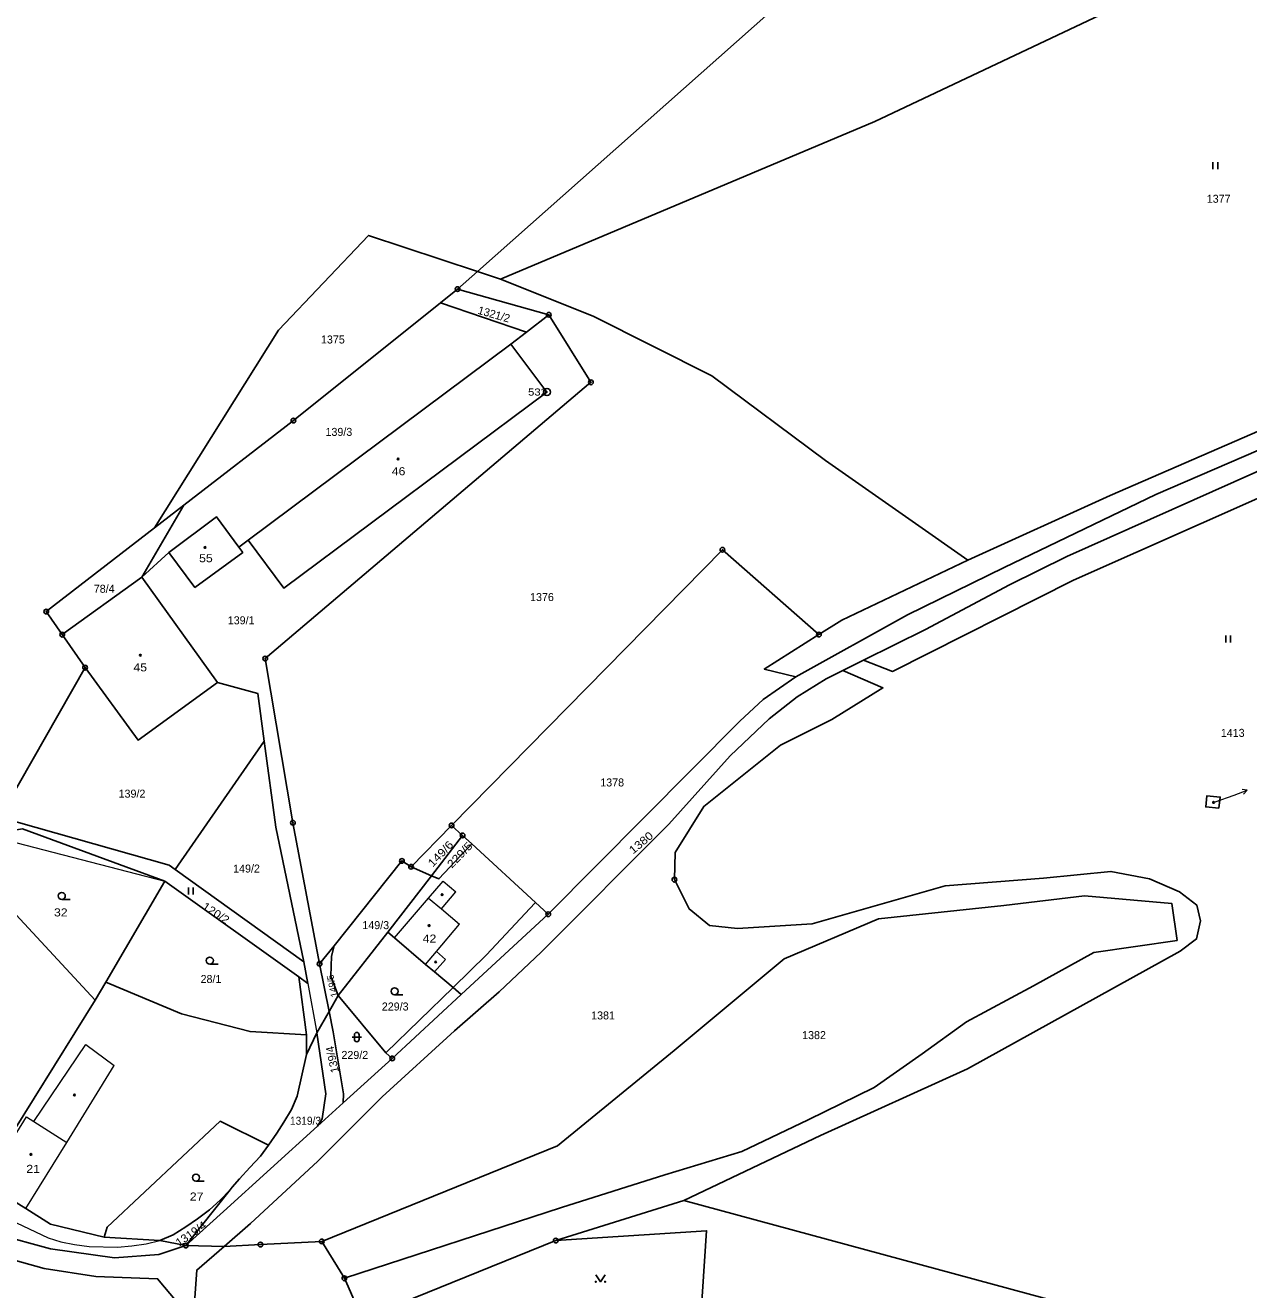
# Model space of a CAD drawing. Extents: x -872229 to -869198, y -1075981 to -1074329.
# Drawn here: x -870924.3 to -870664.3, y -1075205 to -1074936.4 of the extents above; entities that cross this region are included whole.
import ezdxf
from ezdxf.enums import TextEntityAlignment as Align

# ---------------------------------------------------------------- set-up
doc = ezdxf.new("R2010")
doc.units = 0
doc.header["$LTSCALE"] = 0.68
for name, color, linetype, lineweight in [('1', 7, 'Continuous', 25), ('3', 7, 'Continuous', 25), ('4', 7, 'Continuous', 13), ('5', 7, 'Continuous', 25), ('7', 7, 'Continuous', 13), ('8', 7, 'Continuous', 25)]:
    doc.layers.add(name, color=color, linetype=linetype, lineweight=lineweight)
doc.layers.add('2', color=7, linetype='Continuous')

msp = doc.modelspace()

# ---------------------------------------------------------------- linework, layer by layer
at = {"layer": '1'}
for p, q in [((-870832.43, -1074992.44), (-870828.23, -1074988.72)), ((-870828.23, -1074988.72), (-870823.34, -1074990.34)), ((-870832.43, -1074992.44), (-870813.05, -1074997.9)), ((-870817.8, -1075001.55), (-870836.08, -1074995.36)), ((-870821.1, -1075004.1), (-870876.96, -1075045.75)), ((-870890.62, -1075038.35), (-870899.54, -1075053.64)), ((-870896.85, -1075043.16), (-870890.62, -1075038.35)), ((-870876.96, -1075045.75), (-870878.94, -1075047.23)), ((-870893.79, -1075048.39), (-870899.54, -1075053.64)), ((-870916.45, -1075065.85), (-870911.59, -1075072.86)), ((-870837.98, -1075117.09), (-870831.39, -1075108.5)), ((-870892.44, -1075115.73), (-870865.1, -1075135.39)), ((-870837.98, -1075117.09), (-870842.32, -1075115.15)), ((-870857.82, -1075142.49), (-870847.25, -1075129.09)), ((-870858.7, -1075131.95), (-870861.76, -1075135.78)), ((-870907.21, -1075139.69), (-870909.44, -1075143.5)), ((-870857.82, -1075142.49), (-870859.76, -1075145.91)), ((-870856.75, -1075165.32), (-870846.32, -1075155.87)), ((-870862.22, -1075170.28), (-870856.75, -1075165.32)), ((-870784.32, -1075186.07), (-870610.3, -1075233.15)), ((-870907.54, -1075193.83), (-870895.75, -1075194.57)), ((-870895.75, -1075194.57), (-870890.21, -1075195.64)), ((-870890.21, -1075195.64), (-870882.08, -1075195.84)), ((-870856.49, -1075202.6), (-870861.31, -1075194.77))]:
    msp.add_line(p, q, dxfattribs=at)
for points in [[(-870828.23, -1074988.72), (-870733.1, -1074904.34), (-870634.05, -1074816.48)], [(-870823.34, -1074990.34), (-870743.76, -1074956.82), (-870646.76, -1074910.9), (-870624.12, -1074897.23)], [(-870723.96, -1075050), (-870693.71, -1075036.28), (-870649.55, -1075017.06), (-870584.14, -1074987.8), (-870552.32, -1074975.37), (-870546.15, -1074971.5), (-870542.19, -1074967.42)], [(-870896.85, -1075043.16), (-870870.5, -1075001.16), (-870851.34, -1074981.04), (-870828.23, -1074988.72)], [(-870760.55, -1075074.8), (-870736.8, -1075061.65), (-870716.28, -1075051.57), (-870684.01, -1075036.04), (-870643.52, -1075018.55), (-870612.61, -1075004.24), (-870591.23, -1074994.43), (-870570.04, -1074985.9), (-870558.3, -1074982.28), (-870544.73, -1074980.25)], [(-870746.19, -1075071.27), (-870732.98, -1075064.74), (-870715.15, -1075055.28), (-870702.93, -1075049.25), (-870662.75, -1075031.31), (-870646.95, -1075024.02), (-870627.8, -1075016.08), (-870598.46, -1075002.7), (-870582.08, -1074994.97), (-870575.53, -1074992.25), (-870561.97, -1074987.44), (-870555.39, -1074985.35), (-870547.72, -1074984.42), (-870543.16, -1074984.27), (-870536.54, -1074984.58), (-870532.83, -1074984.88), (-870528.68, -1074985.73), (-870515.43, -1074988.43), (-870489.43, -1074993.61)], [(-870723.96, -1075050), (-870735.85, -1075041.72), (-870754.24, -1075028.86), (-870778.4, -1075010.85), (-870803.61, -1074998.16), (-870823.34, -1074990.34)], [(-870890.62, -1075038.35), (-870867.33, -1075020.36), (-870836.08, -1074995.36), (-870832.43, -1074992.44)], [(-870861.76, -1075135.78), (-870867.42, -1075105.8), (-870873.32, -1075070.92), (-870804.09, -1075012.24), (-870813.05, -1074997.9), (-870817.8, -1075001.55), (-870821.1, -1075004.1)], [(-870876.96, -1075045.75), (-870869.36, -1075056), (-870813.44, -1075014.3), (-870821.1, -1075004.1)], [(-870746.19, -1075071.27), (-870740.01, -1075073.65), (-870701.56, -1075054.27), (-870661.14, -1075036.37), (-870626.13, -1075019.06), (-870610.36, -1075011.6)], [(-870916.45, -1075065.85), (-870919.85, -1075060.95), (-870896.85, -1075043.16)], [(-870878.94, -1075047.23), (-870883.7, -1075040.81), (-870893.79, -1075048.39)], [(-870893.79, -1075048.39), (-870888.25, -1075055.83), (-870878.08, -1075048.38), (-870878.94, -1075047.23)], [(-870833.7, -1075106.39), (-870776.15, -1075047.82), (-870755.65, -1075065.84)], [(-870755.65, -1075065.84), (-870750.79, -1075062.78), (-870723.96, -1075050)], [(-870911.59, -1075072.86), (-870900.34, -1075088.23), (-870883.44, -1075076.03), (-870899.54, -1075053.64), (-870916.45, -1075065.85)], [(-870760.55, -1075074.8), (-870767.27, -1075073.18), (-870755.65, -1075065.84)], [(-870882.08, -1075195.84), (-870876.48, -1075190.98), (-870862.11, -1075177.7), (-870848.46, -1075164.05), (-870833.06, -1075150.02), (-870823.61, -1075141.72), (-870814.66, -1075133.34), (-870787.51, -1075106.14), (-870774.51, -1075091.61), (-870766.24, -1075083.76), (-870760.23, -1075079.03), (-870754.08, -1075075.24), (-870750.53, -1075073.45), (-870746.19, -1075071.27)], [(-870930.06, -1075104.56), (-870928.47, -1075102.44), (-870911.59, -1075072.86)], [(-870813.18, -1075125.26), (-870772.47, -1075084.22), (-870767.49, -1075079.65), (-870760.55, -1075074.8)], [(-870784.32, -1075186.07), (-870755.33, -1075172.29), (-870724.06, -1075158.07), (-870678.88, -1075133.11), (-870675.36, -1075130.49), (-870674.52, -1075126.66), (-870675.34, -1075123.32), (-870678.97, -1075120.49), (-870685.35, -1075117.73), (-870693.57, -1075116.15), (-870707.89, -1075117.61), (-870728.84, -1075119.23), (-870757.05, -1075127.29), (-870772.94, -1075128.29), (-870778.87, -1075127.61), (-870783.25, -1075124.12), (-870786.34, -1075117.9), (-870786.18, -1075112.16), (-870780.09, -1075102.34), (-870763.77, -1075089.36), (-870752.86, -1075083.85), (-870742.03, -1075077.18), (-870750.53, -1075073.45)], [(-870883.44, -1075076.03), (-870874.9, -1075078.35), (-870873.52, -1075088.47)], [(-870930.06, -1075104.56), (-870893.7, -1075114.82), (-870892.44, -1075115.73), (-870873.52, -1075088.47)], [(-870873.52, -1075088.47), (-870871.03, -1075106.76), (-870865.1, -1075135.39)], [(-870894.66, -1075118.2), (-870924.88, -1075107.13), (-870932.92, -1075108.35)], [(-870858.7, -1075131.95), (-870844.26, -1075113.92), (-870842.32, -1075115.15), (-870833.7, -1075106.39)], [(-870833.7, -1075106.39), (-870831.39, -1075108.5), (-870829.44, -1075110.29)], [(-870829.44, -1075110.29), (-870836.42, -1075117.76), (-870837.98, -1075117.09)], [(-870829.44, -1075110.29), (-870815.89, -1075122.76), (-870813.18, -1075125.26)], [(-870864.56, -1075150.9), (-870866.19, -1075138.58), (-870894.66, -1075118.2), (-870907.21, -1075139.69)], [(-870837.98, -1075117.09), (-870847.25, -1075129.09), (-870845.84, -1075130.29)], [(-870909.44, -1075143.5), (-870927.17, -1075124.39), (-870932.72, -1075121.96), (-870936.66, -1075131.14), (-870945.89, -1075145.67), (-870949.71, -1075143.97), (-870951.3, -1075148.19), (-870958.37, -1075166.98), (-870949.29, -1075170.31), (-870949.89, -1075171.55)], [(-870861.31, -1075194.77), (-870811.22, -1075174.45), (-870786.41, -1075154.2), (-870763.05, -1075134.75), (-870742.98, -1075126.21), (-870716.31, -1075123.38), (-870699.19, -1075121.37), (-870680.62, -1075122.97), (-870679.5, -1075130.81), (-870697.18, -1075133.41), (-870710, -1075140.48), (-870724.25, -1075148.13), (-870733.72, -1075154.9), (-870743.9, -1075162.08), (-870757.91, -1075168.9), (-870772.04, -1075175.68), (-870788.41, -1075180.62), (-870810.37, -1075187.53), (-870856.49, -1075202.6)], [(-870813.18, -1075125.26), (-870831.64, -1075142.31), (-870846.32, -1075155.87)], [(-870845.84, -1075130.29), (-870839.22, -1075135.9), (-870837.31, -1075137.51), (-870833.4, -1075140.82), (-870831.64, -1075142.31)], [(-870857.82, -1075142.49), (-870859.36, -1075138.42), (-870859.25, -1075134.15), (-870858.7, -1075131.95)], [(-870865.1, -1075135.39), (-870864.25, -1075139.97), (-870866.19, -1075138.58)], [(-870864.56, -1075150.9), (-870864.55, -1075155.07), (-870862.32, -1075150.43), (-870859.76, -1075145.91), (-870861.76, -1075135.78)], [(-870907.21, -1075139.69), (-870891.11, -1075146.44), (-870876.55, -1075150.17), (-870864.56, -1075150.9)], [(-870846.32, -1075155.87), (-870847.68, -1075154.69), (-870857.82, -1075142.49)], [(-870949.89, -1075171.55), (-870931.15, -1075178.18), (-870909.44, -1075143.5)], [(-870856.75, -1075165.32), (-870856.65, -1075163.41), (-870858.9, -1075150.23), (-870859.76, -1075145.91)], [(-870862.32, -1075150.43), (-870860.42, -1075163.37), (-870861.23, -1075168.69), (-870862.22, -1075170.28)], [(-870890.21, -1075195.64), (-870895.9, -1075197.55), (-870905.34, -1075198.25), (-870918.98, -1075196.32), (-870930.4, -1075193.2), (-870939.76, -1075189.14), (-870966.78, -1075174.22), (-871004.43, -1075162.38), (-871023.49, -1075157.84), (-871022.7, -1075155.06)], [(-870864.55, -1075155.07), (-870866.56, -1075163.88), (-870867.75, -1075166.75), (-870869.33, -1075169.39), (-870870.88, -1075171.78), (-870872.64, -1075174.34)], [(-870907.54, -1075193.83), (-870906.89, -1075191.76), (-870882.9, -1075169.23), (-870872.64, -1075174.34)], [(-870890.21, -1075195.64), (-870882.21, -1075188.39), (-870862.22, -1075170.28)], [(-870872.64, -1075174.34), (-870874.32, -1075176.63), (-870876.57, -1075179.07), (-870878.78, -1075181.49), (-870880.31, -1075183.23), (-870880.8, -1075183.78), (-870890.21, -1075195.64)], [(-870931.15, -1075178.18), (-870930.37, -1075178.46), (-870932.82, -1075182.43), (-870924.17, -1075187.79)], [(-870880.8, -1075183.78), (-870882.93, -1075186.01), (-870885.17, -1075188.02), (-870887.7, -1075189.96), (-870890.19, -1075191.67), (-870892.85, -1075193.36), (-870895.75, -1075194.57)], [(-870924.17, -1075187.79), (-870918.98, -1075191.1), (-870907.54, -1075193.83)], [(-870852.61, -1075211.21), (-870811.58, -1075194.57), (-870784.32, -1075186.07)], [(-870811.58, -1075194.57), (-870779.53, -1075192.5), (-870781.56, -1075223.68)], [(-870882.08, -1075195.84), (-870887.87, -1075200.84), (-870890.54, -1075238.17)], [(-870861.31, -1075194.77), (-870874.33, -1075195.43), (-870882.08, -1075195.84)], [(-870925.85, -1075268.83), (-870908.47, -1075274.58), (-870898.66, -1075275.61), (-870893.76, -1075273.35), (-870892.7, -1075270.97), (-870894.88, -1075238.8), (-870892.1, -1075207.59), (-870896.18, -1075202.7), (-870909.34, -1075202.24), (-870920.27, -1075200.54), (-870931.8, -1075197.32)], [(-870852.61, -1075211.21), (-870854.23, -1075207.71), (-870856.49, -1075202.6)]]:
    msp.add_lwpolyline(points, dxfattribs=at)
msp.add_lwpolyline([(-870670.61, -1075102.74), (-870670.36, -1075100.35), (-870673.18, -1075100.06), (-870673.43, -1075102.45)], close=True, dxfattribs=at)
at = {"layer": '3'}
for p, q in [((-870671.891, -1074966.97), (-870671.891, -1074965.47)), ((-870670.89, -1074966.97), (-870670.89, -1074965.47)), ((-870669.151, -1075067.5), (-870669.151, -1075066)), ((-870668.15, -1075067.5), (-870668.15, -1075066)), ((-870889.631, -1075121.08), (-870889.631, -1075119.58)), ((-870888.63, -1075121.08), (-870888.63, -1075119.58)), ((-870916.553, -1075122.11), (-870914.803, -1075122.11)), ((-870885.093, -1075135.85), (-870883.343, -1075135.85)), ((-870845.823, -1075142.37), (-870844.073, -1075142.37)), ((-870854.861, -1075151.341), (-870852.859, -1075151.341)), ((-870854.361, -1075150.841), (-870854.361, -1075151.842)), ((-870853.359, -1075151.842), (-870853.359, -1075150.841)), ((-870888.033, -1075181.95), (-870886.283, -1075181.95))]:
    msp.add_line(p, q, dxfattribs=at)
msp.add_lwpolyline([(-870803.07, -1075201.839), (-870802.07, -1075203.34), (-870801.07, -1075201.839)], dxfattribs=at)
for centre, radius in [((-870916.5529, -1075121.3598), 0.75), ((-870885.0929, -1075135.0998), 0.75), ((-870845.8229, -1075141.6198), 0.75), ((-870888.0329, -1075181.1998), 0.75), ((-870803.07, -1075203.3395), 0.1), ((-870801.07, -1075203.3395), 0.1)]:
    msp.add_circle(centre, radius, dxfattribs=at)
for centre, start, end in [((-870853.86, -1075150.8409), 0, 180), ((-870853.86, -1075151.8409), 180, 359.98789)]:
    msp.add_arc(centre, 0.5, start, end, dxfattribs=at)
at = {"layer": '4'}
for p, q in [((-870932.92, -1075108.35), (-870894.66, -1075118.2)), ((-870838.61, -1075121.81), (-870835.53, -1075118.19)), ((-870835.53, -1075118.19), (-870832.84, -1075120.48)), ((-870835.87, -1075124.13), (-870832.84, -1075120.48)), ((-870845.84, -1075130.29), (-870838.61, -1075121.81)), ((-870838.61, -1075121.81), (-870835.87, -1075124.13)), ((-870816.01, -1075122.88), (-870815.89, -1075122.76)), ((-870835.87, -1075124.13), (-870832.06, -1075127.37)), ((-870836.91, -1075133.15), (-870832.06, -1075127.37)), ((-870839.22, -1075135.9), (-870836.91, -1075133.15)), ((-870836.91, -1075133.15), (-870835.03, -1075134.84)), ((-870837.31, -1075137.51), (-870835.03, -1075134.84)), ((-870864.25, -1075139.97), (-870862.32, -1075150.43)), ((-870847.68, -1075154.69), (-870833.4, -1075140.82)), ((-870922.52, -1075169.25), (-870911.46, -1075152.94)), ((-870911.46, -1075152.94), (-870905.41, -1075157.36)), ((-870915.47, -1075173.71), (-870905.41, -1075157.36)), ((-870930.37, -1075178.46), (-870924.07, -1075168.28)), ((-870924.17, -1075187.79), (-870915.47, -1075173.71)), ((-870936.12, -1075186.16), (-870919.45, -1075194.01)), ((-870919.45, -1075194.01), (-870916.78, -1075194.85)), ((-870916.78, -1075194.85), (-870913.82, -1075195.43)), ((-870913.82, -1075195.43), (-870910.76, -1075195.81)), ((-870910.76, -1075195.81), (-870904.71, -1075195.96)), ((-870898.65, -1075195.28), (-870895.75, -1075194.57))]:
    msp.add_line(p, q, dxfattribs=at)
for points in [[(-870833.4, -1075140.82), (-870826.26, -1075133.88), (-870816.01, -1075122.88)], [(-870924.07, -1075168.28), (-870922.52, -1075169.25), (-870915.47, -1075173.71)], [(-870904.71, -1075195.96), (-870901.65, -1075195.7), (-870898.65, -1075195.28)]]:
    msp.add_lwpolyline(points, dxfattribs=at)
at = {"layer": '5'}
for centre in [(-870845.0668, -1075028.5292), (-870886.1268, -1075047.3192), (-870899.8668, -1075070.2092), (-870671.7668, -1075101.4992), (-870835.7168, -1075121.0792), (-870838.4868, -1075127.6492), (-870837.0968, -1075135.3892), (-870913.8668, -1075163.6392), (-870923.1268, -1075176.2892)]:
    msp.add_circle(centre, 0.175, dxfattribs=at)
at = {"layer": '7'}
msp.add_line((-870664.6, -1075098.904), (-870665.712, -1075098.776), dxfattribs=at)
msp.add_lwpolyline([(-870671.43, -1075101.37), (-870667.42, -1075099.93), (-870664.6, -1075098.904), (-870665.37, -1075099.717)], dxfattribs=at)
at = {"layer": '8'}
for centre, radius in [((-870832.43, -1074992.4399), 0.5), ((-870832.43, -1074992.4399), 0.0303), ((-870813.05, -1074997.8999), 0.5), ((-870813.05, -1074997.8999), 0.0303), ((-870813.44, -1075014.2998), 0.75), ((-870804.09, -1075012.2399), 0.5), ((-870804.09, -1075012.2399), 0.0303), ((-870813.44, -1075014.2998), 0.03), ((-870867.33, -1075020.3599), 0.5), ((-870867.33, -1075020.3599), 0.0303), ((-870776.15, -1075047.8199), 0.5), ((-870776.15, -1075047.8199), 0.0303), ((-870919.85, -1075060.9499), 0.5), ((-870919.85, -1075060.9499), 0.0303), ((-870916.45, -1075065.8499), 0.5), ((-870916.45, -1075065.8499), 0.0303), ((-870755.65, -1075065.8399), 0.5), ((-870755.65, -1075065.8399), 0.0303), ((-870911.59, -1075072.8599), 0.5), ((-870873.32, -1075070.9199), 0.5), ((-870873.32, -1075070.9199), 0.0303), ((-870911.59, -1075072.8599), 0.0303), ((-870867.42, -1075105.7999), 0.5), ((-870867.42, -1075105.7999), 0.0303), ((-870833.7, -1075106.3899), 0.5), ((-870833.7, -1075106.3899), 0.0303), ((-870831.39, -1075108.4999), 0.5), ((-870831.39, -1075108.4999), 0.0303), ((-870844.26, -1075113.9199), 0.5), ((-870844.26, -1075113.9199), 0.0303), ((-870842.32, -1075115.1499), 0.5), ((-870842.32, -1075115.1499), 0.0303), ((-870786.34, -1075117.8999), 0.5), ((-870786.34, -1075117.8999), 0.0303), ((-870813.18, -1075125.2599), 0.5), ((-870813.18, -1075125.2599), 0.0303), ((-870861.76, -1075135.7799), 0.5), ((-870861.76, -1075135.7799), 0.0303), ((-870846.32, -1075155.8699), 0.5), ((-870846.32, -1075155.8699), 0.0303), ((-870890.21, -1075195.6399), 0.5), ((-870890.21, -1075195.6399), 0.0303), ((-870874.33, -1075195.4299), 0.5), ((-870874.33, -1075195.4299), 0.0303), ((-870861.31, -1075194.7699), 0.5), ((-870861.31, -1075194.7699), 0.0303), ((-870811.58, -1075194.5699), 0.5), ((-870811.58, -1075194.5699), 0.0303), ((-870856.49, -1075202.5999), 0.5), ((-870856.49, -1075202.5999), 0.0303)]:
    msp.add_circle(centre, radius, dxfattribs=at)

# ---------------------------------------------------------------- texts
at = {"layer": '2'}
for s, p in [('1377', (-870673.21, -1074974.09)), ('1375', (-870861.47, -1075003.99)), ('139/3', (-870860.51, -1075023.62)), ('78/4', (-870909.76, -1075056.95)), ('1376', (-870817.03, -1075058.71)), ('139/1', (-870881.28, -1075063.65)), ('1413', (-870670.22, -1075087.56)), ('1378', (-870802.11, -1075098.1)), ('139/2', (-870904.48, -1075100.48)), ('149/2', (-870880.14, -1075116.39)), ('149/3', (-870852.68, -1075128.41)), ('28/1', (-870887.06, -1075139.86)), ('229/3', (-870848.54, -1075145.7)), ('1381', (-870804.05, -1075147.6)), ('1382', (-870759.21, -1075151.78)), ('229/2', (-870857.12, -1075155.99))]:
    msp.add_text(s, height=1.7, dxfattribs=at).set_placement(p)
for s, height, rotation, p in [('1321/2', 1.7, 344, (-870828.274, -1074997.647)), ('149/5', 1.445, 102, (-870857.863, -1075142.699)), ('139/4', 1.7, 102, (-870857.638, -1075158.733))]:
    msp.add_text(s, height=height, rotation=rotation, dxfattribs=at).set_placement(p)
for s, width, p in [('46', 1.15, (-870846.43, -1075031.98)), ('55', 1.15, (-870887.38, -1075050.46)), ('45', 1.15, (-870901.34, -1075073.65)), ('32', 1.15, (-870918.22, -1075125.71)), ('42', 1.15, (-870839.86, -1075131.27)), ('1319/3', 0.95, (-870868.06, -1075169.97)), ('21', 1.15, (-870924.1, -1075180.19)), ('27', 1.15, (-870889.35, -1075186.07))]:
    msp.add_text(s, height=1.7, dxfattribs=dict(at, width=width)).set_placement(p)
for s, rotation, width, p in [('149/6', 46, 1.15, (-870837.718, -1075115.35)), ('229/5', 46, 1.15, (-870833.638, -1075115.59)), ('1380', 40, 1.15, (-870795.133, -1075112.571)), ('120/2', 327, 1.1, (-870886.882, -1075124.012)), ('1319/4', 35, 1.05, (-870891.612, -1075195.916))]:
    msp.add_text(s, height=1.7, rotation=rotation, dxfattribs=dict(at, width=width)).set_placement(p)
at = {"layer": '8', "width": 1.2}
msp.add_text('532', height=1.5, dxfattribs=at).set_placement((-870813.44, -1075015.05), align=Align.RIGHT)

doc.saveas('drawing.dxf')
